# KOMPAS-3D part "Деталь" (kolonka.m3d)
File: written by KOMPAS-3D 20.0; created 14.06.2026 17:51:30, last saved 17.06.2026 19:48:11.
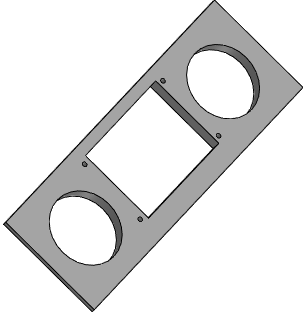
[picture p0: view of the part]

Document properties: Полное имя файла: D:\myProjects\Progect_esp32\box_compas\kolonka.m3d

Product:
- Part/product: Деталь
    Масса: 0.430655

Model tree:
1. Эскиз:1
2. Элемент выдавливания:1
     Расстояние 1 = 8
3. Фаска:1  (with: Элемент выдавливания:1)
     Угол = 45; Длина 1 = 5; Длина 2 = 5
4. Эскиз:2  (with: Элемент выдавливания:1)
5. Элемент выдавливания:2
     Расстояние 2 = 8
6. Эскиз:3  (with: Элемент выдавливания:1)
7. Элемент выдавливания:3
     Расстояние 2 = 8
8. Массив по сетке:2  (with: Элемент выдавливания:3, Эскиз:3, Элемент выдавливания:1)  (4 pattern instances)
     Шаг 1 = 77; Угол раствора = -90; Шаг 2 = 44
9. Эскиз:4  (with: Элемент выдавливания:1)
10. Элемент выдавливания:4
     Расстояние 2 = 8

Referenced files in D:\myProjects\Progect_esp32\box_compas\: Сборка_front_panel.a3d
